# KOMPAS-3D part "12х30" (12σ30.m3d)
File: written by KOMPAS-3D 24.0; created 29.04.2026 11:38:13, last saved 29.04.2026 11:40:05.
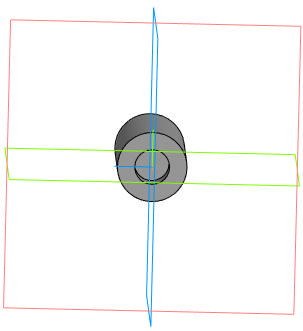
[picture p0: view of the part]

Document properties: Автор: USG_411; Полное имя файла: C:\Users\USG_411\Desktop\ИА-2904_411-12\12х30.m3d

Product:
- Part/product: 12х30
    Масса: 0.023989

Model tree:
1. Эскиз:1
2. Элемент выдавливания:1
     Расстояние 2 = 30
3. Эскиз:2  (with: Грань.Элемент выдавливания:1)
4. Элемент выдавливания:2
     Расстояние 2 = 6
5. Эскиз:3  (with: Грань.Элемент выдавливания:1)
6. Элемент выдавливания:3
     Расстояние 2 = 6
